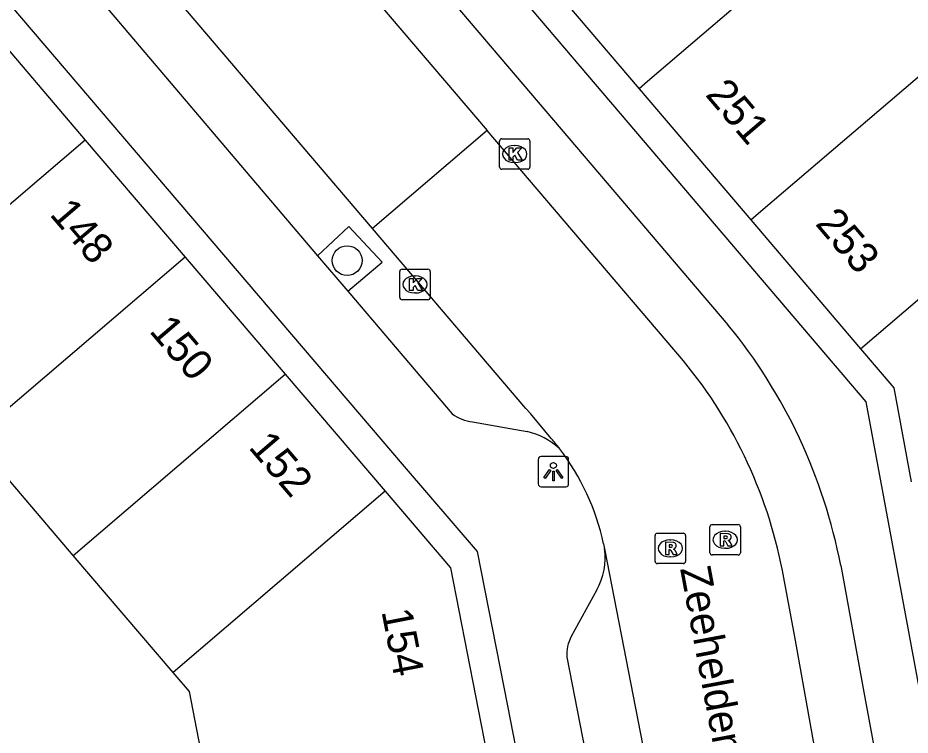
# Model space of a CAD drawing. Extents: x 160379 to 161131, y 383940 to 384849.
# Drawn here: x 160789.14 to 160818.43, y 384580.67 to 384604.2 of the extents above; entities that cross this region are included whole.
import ezdxf

# ---------------------------------------------------------------- set-up
doc = ezdxf.new("R2010")
doc.units = 0
for name, color, linetype in [('IMGEO_Boom', 7, 'Continuous'), ('IMGEO_Kolk', 7, 'Continuous'), ('IMGEO_Lichtpunt', 7, 'Continuous'), ('IMGEO_Openbare_ruimte_label', 7, 'Continuous'), ('IMGEO_Pand', 7, 'Continuous'), ('IMGEO_Pand_nummerreeks', 7, 'Continuous'), ('IMGEO_Parkeervlak_open', 7, 'Continuous'), ('IMGEO_Rijbaan_lokaal_open', 7, 'Continuous'), ('IMGEO_Rioolput', 7, 'Continuous'), ('IMGEO_Voetpad_open', 7, 'Continuous')]:
    doc.layers.add(name, color=color, linetype=linetype)

msp = doc.modelspace()

# ---------------------------------------------------------------- linework, layer by layer
at = {"layer": 'IMGEO_Boom'}
msp.add_circle((160799.949, 384596.235), 0.489, dxfattribs=at)
at = {"layer": 'IMGEO_Kolk'}
for p, q in [((160804.947, 384599.305), (160804.947, 384600.157)), ((160805.022, 384600.231), (160805.874, 384600.231)), ((160805.948, 384600.157), (160805.948, 384599.305)), ((160805.435, 384600.011), (160805.46, 384600.011)), ((160805.458, 384599.451), (160805.433, 384599.451)), ((160805.874, 384599.231), (160805.022, 384599.231)), ((160801.749, 384595.953), (160802.601, 384595.953)), ((160801.674, 384595.027), (160801.674, 384595.879)), ((160802.162, 384595.733), (160802.187, 384595.733)), ((160802.675, 384595.879), (160802.675, 384595.027)), ((160802.185, 384595.173), (160802.16, 384595.173)), ((160802.601, 384594.953), (160801.749, 384594.953))]:
    msp.add_line(p, q, dxfattribs=at)
for points in [[(160804.947, 384599.305), (160804.947, 384600.157)], [(160805.022, 384600.231), (160805.874, 384600.231)], [(160805.948, 384600.157), (160805.948, 384599.305)], [(160805.268, 384599.931), (160805.391, 384599.931), (160805.391, 384599.78), (160805.521, 384599.931), (160805.685, 384599.931), (160805.539, 384599.78), (160805.692, 384599.531), (160805.54, 384599.531), (160805.455, 384599.695), (160805.391, 384599.628), (160805.391, 384599.531), (160805.268, 384599.531), (160805.268, 384599.931)], [(160805.874, 384599.231), (160805.022, 384599.231)], [(160801.749, 384595.953), (160802.601, 384595.953)], [(160801.674, 384595.027), (160801.674, 384595.879)], [(160801.995, 384595.653), (160802.118, 384595.653), (160802.118, 384595.502), (160802.248, 384595.653), (160802.412, 384595.653), (160802.266, 384595.502), (160802.419, 384595.253), (160802.267, 384595.253), (160802.182, 384595.417), (160802.118, 384595.35), (160802.118, 384595.253), (160801.995, 384595.253), (160801.995, 384595.653)], [(160802.675, 384595.879), (160802.675, 384595.027)], [(160802.601, 384594.953), (160801.749, 384594.953)]]:
    msp.add_lwpolyline(points, dxfattribs=at)
for centre, start, end in [((160805.024, 384600.155), 91.552, 178.448), ((160805.024, 384600.155), 91.552, 178.448), ((160805.872, 384600.155), 1.552, 88.448), ((160805.872, 384600.155), 1.552, 88.448), ((160805.024, 384599.307), 181.552, 268.448), ((160805.024, 384599.307), 181.552, 268.448), ((160805.872, 384599.307), 271.552, 358.448), ((160805.872, 384599.307), 271.552, 358.448), ((160801.751, 384595.877), 91.552, 178.448), ((160801.751, 384595.877), 91.552, 178.448), ((160802.599, 384595.877), 1.552, 88.448), ((160802.599, 384595.877), 1.552, 88.448), ((160801.751, 384595.029), 181.552, 268.448), ((160801.751, 384595.029), 181.552, 268.448), ((160802.599, 384595.029), 271.552, 358.448), ((160802.599, 384595.029), 271.552, 358.448)]:
    msp.add_arc(centre, 0.0765, start, end, dxfattribs=at)
for centre, major_axis, ratio, start_param, end_param in [((160805.434, 384599.731), (-0.387, 0.002), 0.722429, 4.712389, 7.853982), ((160805.459, 384599.731), (-0.39, 0.002), 0.717154, 1.570796, 4.712389), ((160802.161, 384595.453), (-0.387, 0.002), 0.722429, 4.712389, 7.853982), ((160802.186, 384595.453), (-0.39, 0.002), 0.717154, 1.570796, 4.712389)]:
    msp.add_ellipse(centre, major_axis=major_axis, ratio=ratio, start_param=start_param, end_param=end_param, dxfattribs=at)
at = {"layer": 'IMGEO_Lichtpunt'}
for p, q in [((160807.121, 384589.81), (160806.313, 384589.81)), ((160807.121, 384589.81), (160806.313, 384589.81)), ((160806.219, 384589.715), (160806.219, 384588.908)), ((160806.219, 384589.715), (160806.219, 384588.908)), ((160807.215, 384588.908), (160807.215, 384589.715)), ((160807.215, 384588.908), (160807.215, 384589.715)), ((160806.313, 384588.814), (160807.121, 384588.814)), ((160806.313, 384588.814), (160807.121, 384588.814))]:
    msp.add_line(p, q, dxfattribs=at)
for points in [[(160806.593, 384589.379), (160806.632, 384589.351), (160806.444, 384589.089), (160806.406, 384589.116), (160806.593, 384589.379)], [(160806.695, 384589.331), (160806.742, 384589.331), (160806.742, 384589.009), (160806.695, 384589.009), (160806.695, 384589.331)], [(160806.805, 384589.351), (160806.843, 384589.378), (160807.03, 384589.116), (160806.991, 384589.088), (160806.805, 384589.351)]]:
    msp.add_lwpolyline(points, dxfattribs=at)
msp.add_circle((160806.718, 384589.513), 0.0994, dxfattribs=at)
for centre, start, end in [((160806.313, 384589.715), 90, 180), ((160806.313, 384589.715), 90, 180), ((160807.121, 384589.715), 0, 90), ((160807.121, 384589.715), 0, 90), ((160806.313, 384588.908), 180, 270), ((160806.313, 384588.908), 180, 270), ((160807.121, 384588.908), 270, 0), ((160807.121, 384588.908), 270, 360)]:
    msp.add_arc(centre, 0.0946, start, end, dxfattribs=at)
at = {"layer": 'IMGEO_Pand'}
for points in [[(160819.298, 384610.084), (160818.369, 384609.291), (160816.489, 384607.817), (160809.802, 384602.108), (160809.528, 384601.874)], [(160805.909, 384606.122), (160809.528, 384601.874)], [(160788.067, 384604.033), (160791.349, 384600.191)], [(160813.196, 384597.57), (160813.453, 384597.789), (160820.154, 384603.511)], [(160809.528, 384601.874), (160813.196, 384597.57)], [(160791.349, 384600.191), (160784.391, 384594.248)], [(160791.349, 384600.191), (160794.631, 384596.35)], [(160816.799, 384593.342), (160823.755, 384599.281)], [(160813.196, 384597.57), (160816.799, 384593.342)], [(160794.631, 384596.35), (160787.673, 384590.406)], [(160794.631, 384596.35), (160797.913, 384592.508)], [(160816.799, 384593.342), (160817.887, 384592.065), (160818.461, 384588.975)], [(160790.955, 384586.564), (160797.913, 384592.508)], [(160797.913, 384592.508), (160801.195, 384588.667)], [(160790.955, 384586.564), (160787.673, 384590.406)], [(160801.195, 384588.667), (160794.236, 384582.722)], [(160801.195, 384588.667), (160803.34, 384586.156), (160804.705, 384579.154)], [(160794.236, 384582.722), (160790.955, 384586.564)], [(160795.673, 384577.454), (160794.768, 384582.1), (160794.236, 384582.722)]]:
    msp.add_lwpolyline(points, dxfattribs=at)
at = {"layer": 'IMGEO_Parkeervlak_open'}
msp.add_lwpolyline([(160799.972, 384595.231), (160801.093, 384596.179), (160800.006, 384597.358), (160798.979, 384596.397)], dxfattribs=at)
at = {"layer": 'IMGEO_Rijbaan_lokaal_open'}
for points in [[(160795.82, 384610.729), (160804.54, 384600.506)], [(160800.781, 384597.292), (160792.118, 384607.459)], [(160804.54, 384600.506), (160800.781, 384597.292)], [(160810.989, 384592.947), (160804.54, 384600.506)], [(160806.649, 384590.394), (160805.962, 384591.216), (160805.813, 384591.386), (160800.781, 384597.292)], [(160808.366, 384586.942), (160808.395, 384586.778)], [(160808.395, 384586.778), (160818.024, 384537.321)], [(160818.551, 384562.065), (160814.64, 384583.89), (160814.28, 384585.825)]]:
    msp.add_lwpolyline(points, dxfattribs=at)
for centre, radius, start, end in [((160799.002, 384583.087), 15.521, 10.1613, 39.441), ((160801.557, 384585.963), 6.75, 37.4896, 41.0312), ((160800.725, 384585.296), 7.816, 12.1585, 37.6586)]:
    msp.add_arc(centre, radius, start, end, dxfattribs=at)
at = {"layer": 'IMGEO_Rioolput'}
for p, q in [((160811.855, 384586.651), (160811.855, 384587.503)), ((160811.93, 384587.577), (160812.782, 384587.577)), ((160812.856, 384587.503), (160812.856, 384586.651)), ((160810.055, 384586.367), (160810.055, 384587.219)), ((160810.13, 384587.293), (160810.982, 384587.293)), ((160811.056, 384587.219), (160811.056, 384586.367)), ((160812.343, 384587.357), (160812.368, 384587.357)), ((160810.543, 384587.073), (160810.568, 384587.073)), ((160812.782, 384586.577), (160811.93, 384586.577)), ((160812.366, 384586.797), (160812.341, 384586.797)), ((160810.982, 384586.293), (160810.13, 384586.293)), ((160810.566, 384586.513), (160810.541, 384586.513))]:
    msp.add_line(p, q, dxfattribs=at)
for points in [[(160811.855, 384586.651), (160811.855, 384587.503)], [(160811.93, 384587.577), (160812.782, 384587.577)], [(160812.856, 384587.503), (160812.856, 384586.651)], [(160810.055, 384586.367), (160810.055, 384587.219)], [(160810.13, 384587.293), (160810.982, 384587.293)], [(160811.056, 384587.219), (160811.056, 384586.367)], [(160812.444, 384587.275), (160812.192, 384587.277), (160812.192, 384586.877)], [(160812.37, 384587.196), (160812.316, 384587.196), (160812.316, 384587.115)], [(160810.644, 384586.991), (160810.392, 384586.993), (160810.392, 384586.593)], [(160810.57, 384586.912), (160810.516, 384586.912), (160810.516, 384586.831)], [(160812.192, 384586.877), (160812.316, 384586.877), (160812.316, 384587.039), (160812.327, 384587.039)], [(160812.316, 384587.115), (160812.368, 384587.115)], [(160812.374, 384587.01), (160812.445, 384586.877), (160812.585, 384586.877), (160812.52, 384587.003)], [(160810.392, 384586.593), (160810.516, 384586.593), (160810.516, 384586.755), (160810.527, 384586.755)], [(160810.516, 384586.831), (160810.568, 384586.831)], [(160810.574, 384586.726), (160810.645, 384586.593), (160810.785, 384586.593), (160810.72, 384586.719)], [(160812.782, 384586.577), (160811.93, 384586.577)], [(160810.982, 384586.293), (160810.13, 384586.293)]]:
    msp.add_lwpolyline(points, dxfattribs=at)
for centre, radius, start, end in [((160811.932, 384587.501), 0.0765, 91.552, 178.448), ((160811.932, 384587.501), 0.0765, 91.552, 178.448), ((160812.78, 384587.501), 0.0765, 1.552, 88.448), ((160812.78, 384587.501), 0.0765, 1.552, 88.448), ((160810.132, 384587.217), 0.0765, 91.552, 178.448), ((160810.132, 384587.217), 0.0765, 91.552, 178.448), ((160810.98, 384587.217), 0.0765, 1.552, 88.448), ((160810.98, 384587.217), 0.0765, 1.552, 88.448), ((160812.376, 384587.1), 0.0964, 77.0061, 93.1865), ((160812.39, 384587.157), 0.0378, 276.6634, 79.6772), ((160812.443, 384587.165), 0.109, 350.3612, 89.416), ((160812.441, 384587.165), 0.112, 277.5842, 350.9817), ((160810.576, 384586.816), 0.0964, 77.0061, 93.1865), ((160810.59, 384586.873), 0.0378, 276.6634, 79.6772), ((160810.643, 384586.881), 0.109, 350.3612, 89.416), ((160810.641, 384586.881), 0.112, 277.5842, 350.9817), ((160812.326, 384586.986), 0.0533, 26.0293, 88.6989), ((160812.352, 384587.304), 0.19, 274.7715, 282.9687), ((160812.425, 384586.95), 0.108, 29.5134, 73.7905), ((160810.526, 384586.702), 0.0533, 26.0293, 88.6989), ((160810.552, 384587.02), 0.19, 274.7715, 282.9687), ((160810.625, 384586.666), 0.108, 29.5134, 73.7905), ((160811.932, 384586.653), 0.0765, 181.552, 268.448), ((160811.932, 384586.653), 0.0765, 181.552, 268.448), ((160812.78, 384586.653), 0.0765, 271.552, 358.448), ((160812.78, 384586.653), 0.0765, 271.552, 358.448), ((160810.132, 384586.369), 0.0765, 181.552, 268.448), ((160810.132, 384586.369), 0.0765, 181.552, 268.448), ((160810.98, 384586.369), 0.0765, 271.552, 358.448), ((160810.98, 384586.369), 0.0765, 271.552, 358.448)]:
    msp.add_arc(centre, radius, start, end, dxfattribs=at)
for centre, major_axis, ratio, start_param, end_param in [((160812.342, 384587.077), (-0.387, 0.002), 0.722429, 4.712389, 7.853982), ((160812.367, 384587.077), (-0.39, 0.002), 0.717154, 1.570796, 4.712389), ((160810.542, 384586.793), (-0.387, 0.002), 0.722429, 4.712389, 7.853982), ((160810.567, 384586.793), (-0.39, 0.002), 0.717154, 1.570796, 4.712389)]:
    msp.add_ellipse(centre, major_axis=major_axis, ratio=ratio, start_param=start_param, end_param=end_param, dxfattribs=at)
at = {"layer": 'IMGEO_Voetpad_open'}
for points in [[(160824.919, 384548.707), (160818.812, 384581.761), (160816.984, 384591.607), (160750.44, 384669.667)], [(160752.443, 384664.534), (160812.448, 384594.132)], [(160814.707, 384533.039), (160805.221, 384581.626), (160804.227, 384586.696), (160801.827, 384589.484), (160785.555, 384608.533), (160784.593, 384609.659), (160759.221, 384639.361), (160756.612, 384642.415), (160753.096, 384646.531), (160752.089, 384647.71), (160738.611, 384663.488)], [(160791.95, 384604.656), (160798.979, 384596.397)], [(160798.979, 384596.397), (160799.972, 384595.231)], [(160799.972, 384595.231), (160803.397, 384591.205)], [(160804.067, 384590.945), (160805.852, 384590.628)], [(160816.147, 384586.236), (160816.904, 384582.075), (160819.973, 384565.541)], [(160808.146, 384585.436), (160807.303, 384583.902)], [(160807.162, 384583.224), (160808.442, 384576.668)]]:
    msp.add_lwpolyline(points, dxfattribs=at)
for centre, radius, start, end in [((160798.728, 384582.89), 17.737, 10.8725, 39.3304), ((160804.265, 384592.449), 1.517, 235.0855, 262.496), ((160805.338, 384588.361), 2.325, 47.3656, 77.2376), ((160806.252, 384586.481), 2.163, 331.0979, 7.8794), ((160808.401, 384583.32), 1.242, 152.0701, 184.4338)]:
    msp.add_arc(centre, radius, start, end, dxfattribs=at)

# ---------------------------------------------------------------- texts
at = {"layer": 'IMGEO_Openbare_ruimte_label'}
msp.add_text('Zeeheldenlaan', height=1, rotation=280.6021, dxfattribs=at).set_placement((160810.873, 384586.131))
at = {"layer": 'IMGEO_Pand_nummerreeks'}
for s, rotation, p in [('251', 310.4334, (160811.677, 384601.667)), ('148', 310.5079, (160790.153, 384597.743)), ('253', 310.4334, (160815.286, 384597.432)), ('150', 310.5079, (160793.424, 384593.915)), ('152', 310.5079, (160796.682, 384590.1)), ('154', 281.0292, (160801.071, 384584.729))]:
    msp.add_text(s, height=1, rotation=rotation, dxfattribs=at).set_placement(p)

doc.saveas('drawing.dxf')
